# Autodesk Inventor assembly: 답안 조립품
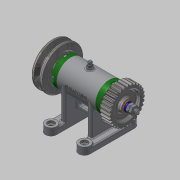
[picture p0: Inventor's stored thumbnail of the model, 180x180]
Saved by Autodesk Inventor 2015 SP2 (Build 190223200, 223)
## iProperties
Created: 2015-11
Part Number: 답안 조립품
Document SubType Name: Assembly
Designer: AMC
Author: AMC
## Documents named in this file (16)
- C:\Users\AMC\Desktop\451109V1031\답안 조립품.iam
- C:\Users\AMC\Desktop\451109V1031\본체.ipt
- C:\Users\AMC\Desktop\451109V1031\V벨트풀리.ipt
- C:\Users\AMC\Desktop\451109V1031\베어링 15 x 32 x 9.ipt
- C:\Users\AMC\Desktop\451109V1031\축.ipt
- C:\Users\AMC\Desktop\451109V1031\커버.ipt
- C:\Users\AMC\Desktop\451109V1031\오일 실 15 25 7.ipt
- C:\Users\AMC\Desktop\451109V1031\키 3 x 3 x 12.ipt
- C:\Users\AMC\Desktop\451109V1031\스퍼기어.ipt
- C:\Users\AMC\Desktop\451109V1031\스프링와셔 8.ipt
- C:\Users\AMC\Desktop\451109V1031\와셔 8x17.ipt
- C:\Users\AMC\Desktop\451109V1031\너트 M 8.ipt
- C:\Users\AMC\Desktop\451109V1031\볼트 M 6 x 8.ipt
- C:\Users\AMC\Desktop\451109V1031\와셔 6x11.5.ipt
- C:\Users\AMC\Desktop\451109V1031\니플 M 6 x 0.75.ipt
- C:\Users\AMC\Desktop\451109V1031\볼트 M4 x 12.ipt
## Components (11 placed, 3 different names)
1. V벨트풀리:1
2. KS B 2023 6002 - 15 x 32 x 9:1
3. KS B 2023 6002 - 15 x 32 x 9:2
4. ISO 4762 M4 x 12:1
5. ISO 4762 M4 x 12:2
6. ISO 4762 M4 x 12:3
7. ISO 4762 M4 x 12:4
8. ISO 4762 M4 x 12:5
9. ISO 4762 M4 x 12:6
10. ISO 4762 M4 x 12:7
11. ISO 4762 M4 x 12:8
